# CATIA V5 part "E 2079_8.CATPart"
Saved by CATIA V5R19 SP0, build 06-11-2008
Nomenclature: E 2079_8
Description: PART-E 2079_8-DESC
Property "Hersteller": "Meusburger"
Property "Material": "2.0401 / FPM (Viton)"
Property "Bestellnummer": "E2079/8"
Property "Teilenummer": "E2079/8"
Property "Beschreibung": "Verschlussstopfen mit O-Ring _ Plug with O-ring seal"
Material "Brass": density 8216 kg/m3, Young's modulus 1.31e+11 Pa, Poisson ratio 0.35, thermal expansion 1.67e-05 1/K
Bounding box of the stored display mesh (mm): x -4 to 4, y -3.991 to 3.991, z -10 to 0
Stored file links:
  G:\UTB\Kombinované\Bakalářská práce\Catia\FORMA\E 2079_8.CATPart
  D:\Aplikace\CATIA\Nová složka\win_b64\startup\materials\Catalog.CATMaterial
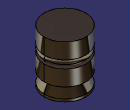
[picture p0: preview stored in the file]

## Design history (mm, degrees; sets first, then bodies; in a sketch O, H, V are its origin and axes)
Body1 "E 2079_8" (main body)
  Solid1: solid without history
